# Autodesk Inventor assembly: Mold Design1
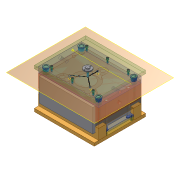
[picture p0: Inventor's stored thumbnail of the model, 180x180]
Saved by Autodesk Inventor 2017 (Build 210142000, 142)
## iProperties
Created: 2016-07
Part Number: Mold Design1
Document SubType Name: Assembly
Designer: Sandeep
Author: Sandeep
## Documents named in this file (7)
- C:\Inventor_2017\c19\Mold Design1.iam
- C:\Inventor_2017\c19\Mold Design1_c19_Inv_tut01_LY.iam
- C:\Inventor_2017\c19\Mold Design1_RG.ipt
- C:\Inventor_2017\c19\MB\FUTABA_SA-S 3\Mold Design1_MB.iam
- C:\Inventor_2017\c19\Sprue Bushing\DME_AGN\Mold Design1_AGN 76-3.5-0.ipt
- C:\Inventor_2017\c19\Locating Ring\RABOURDIN_646 - Type B\Mold Design1_646-90-25-12.5.ipt
- C:\Inventor_2017\c19\Mold Design1_CH.ipt
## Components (6 placed, 6 different names)
1. Mold Design1_c19_Inv_tut01_LY:1 [sub-assembly] — Flush:1, Flush:2, Flush:3, Flush:4, Flush:5, Flush:11
2. Mold Design1_RG:1 — Flush:6, Flush:7, Flush:8, Flush:10, Mate:3
3. Mold Design1_MB:1 [sub-assembly] — Flush:11, Mate:1, Angle:1, Mate:2, Mate:4
4. Mold Design1_AGN 76-3.5-0:1 — Mate:2, Mate:3, Mate:5
5. Mold Design1_646-90-25-12.5:1 — Mate:4, Mate:5
6. Mold Design1_CH:1
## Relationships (16: Flush 10, Mate 5, Angle 1)
- Flush:1: Mold Design1_c19_Inv_tut01_LY:1
- Flush:2: Mold Design1_c19_Inv_tut01_LY:1
- Flush:3: Mold Design1_c19_Inv_tut01_LY:1
- Flush:4: Mold Design1_c19_Inv_tut01_LY:1
- Flush:5: Mold Design1_c19_Inv_tut01_LY:1
- Flush:6: Mold Design1_RG:1
- Flush:7: Mold Design1_RG:1
- Flush:8: Mold Design1_RG:1
- Flush:10: Mold Design1_RG:1
- Flush:11: Mold Design1_c19_Inv_tut01_LY:1 ↔ Mold Design1_MB:1
- Mate:1: Mold Design1_MB:1
- Angle:1: Mold Design1_MB:1
- Mate:2: Mold Design1_MB:1 ↔ Mold Design1_AGN 76-3.5-0:1
- Mate:3: Mold Design1_RG:1 ↔ Mold Design1_AGN 76-3.5-0:1
- Mate:4: Mold Design1_MB:1 ↔ Mold Design1_646-90-25-12.5:1
- Mate:5: Mold Design1_AGN 76-3.5-0:1 ↔ Mold Design1_646-90-25-12.5:1
